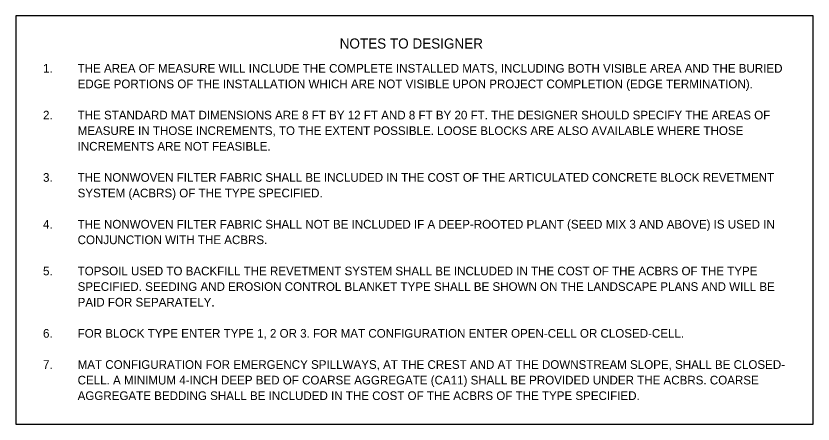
# Model space of a CAD drawing. Extents: x 0 to 0.921, y -0.471 to 0.
import ezdxf

# ---------------------------------------------------------------- set-up
doc = ezdxf.new("R2010")
doc.units = 0
doc.layers.add('HS_Dimensions_and_Text', color=7, linetype='Continuous')
doc.layers.add('HS_Notes_to_Designer_Outline-ILTollway', color=7, linetype='Continuous')

msp = doc.modelspace()

# ---------------------------------------------------------------- linework, layer by layer
at = {"layer": 'HS_Notes_to_Designer_Outline-ILTollway'}
msp.add_lwpolyline([(0.00003, -0.47119), (0.92097, -0.47119), (0.92097, 0), (0.00003, 0)], close=True, dxfattribs=at)

# ---------------------------------------------------------------- texts
at = {"layer": 'HS_Dimensions_and_Text'}
for s, height, p in [('NOTES TO DESIGNER', 0.0116667, (0.37403, -0.03763)), ('1.', 0.01, (0.03131, -0.06547)), ('THE AREA OF MEASURE WILL INCLUDE THE COMPLETE INSTALLED MATS, INCLUDING BOTH VISIBLE AREA AND THE BURIED ', 0.01, (0.07131, -0.06547)), ('EDGE PORTIONS OF THE INSTALLATION WHICH ARE NOT VISIBLE UPON PROJECT COMPLETION (EDGE TERMINATION).', 0.01, (0.07131, -0.08347)), ('2.', 0.01, (0.03131, -0.11947)), ('THE STANDARD MAT DIMENSIONS ARE 8 FT BY 12 FT AND 8 FT BY 20 FT. THE DESIGNER SHOULD SPECIFY THE AREAS OF ', 0.01, (0.07131, -0.11947)), ('MEASURE IN THOSE INCREMENTS, TO THE EXTENT POSSIBLE. LOOSE BLOCKS ARE ALSO AVAILABLE WHERE THOSE ', 0.01, (0.07131, -0.13747)), ('INCREMENTS ARE NOT FEASIBLE.', 0.01, (0.07131, -0.15547)), ('3.', 0.01, (0.03131, -0.19147)), ('THE NONWOVEN FILTER FABRIC SHALL BE INCLUDED IN THE COST OF THE ARTICULATED CONCRETE BLOCK REVETMENT ', 0.01, (0.07131, -0.19147)), ('SYSTEM (ACBRS) OF THE TYPE SPECIFIED.', 0.01, (0.07131, -0.20947)), ('4.', 0.01, (0.03131, -0.24547)), ('THE NONWOVEN FILTER FABRIC SHALL NOT BE INCLUDED IF A DEEP-ROOTED PLANT (SEED MIX 3 AND ABOVE) IS USED IN ', 0.01, (0.07131, -0.24547)), ('CONJUNCTION WITH THE ACBRS.', 0.01, (0.07131, -0.26347)), ('5.', 0.01, (0.03131, -0.29947)), ('TOPSOIL USED TO BACKFILL THE REVETMENT SYSTEM SHALL BE INCLUDED IN THE COST OF THE ACBRS OF THE TYPE ', 0.01, (0.07131, -0.29947)), ('SPECIFIED. SEEDING AND EROSION CONTROL BLANKET TYPE SHALL BE SHOWN ON THE LANDSCAPE PLANS AND WILL BE ', 0.01, (0.07131, -0.31747)), ('PAID FOR SEPARATELY.', 0.01, (0.07131, -0.33547)), ('6.', 0.01, (0.03131, -0.37147)), ('FOR BLOCK TYPE ENTER TYPE 1, 2 OR 3. FOR MAT CONFIGURATION ENTER OPEN-CELL OR CLOSED-CELL.', 0.01, (0.07131, -0.37147)), ('7.', 0.01, (0.03131, -0.40747)), ('MAT CONFIGURATION FOR EMERGENCY SPILLWAYS, AT THE CREST AND AT THE DOWNSTREAM SLOPE, SHALL BE CLOSED-', 0.01, (0.07131, -0.40747)), ('CELL. A MINIMUM 4-INCH DEEP BED OF COARSE AGGREGATE (CA11) SHALL BE PROVIDED UNDER THE ACBRS. COARSE ', 0.01, (0.07131, -0.42547)), ('AGGREGATE BEDDING SHALL BE INCLUDED IN THE COST OF THE ACBRS OF THE TYPE SPECIFIED. ', 0.01, (0.07131, -0.44347))]:
    msp.add_text(s, height=height, dxfattribs=at).set_placement(p)

doc.saveas('drawing.dxf')
